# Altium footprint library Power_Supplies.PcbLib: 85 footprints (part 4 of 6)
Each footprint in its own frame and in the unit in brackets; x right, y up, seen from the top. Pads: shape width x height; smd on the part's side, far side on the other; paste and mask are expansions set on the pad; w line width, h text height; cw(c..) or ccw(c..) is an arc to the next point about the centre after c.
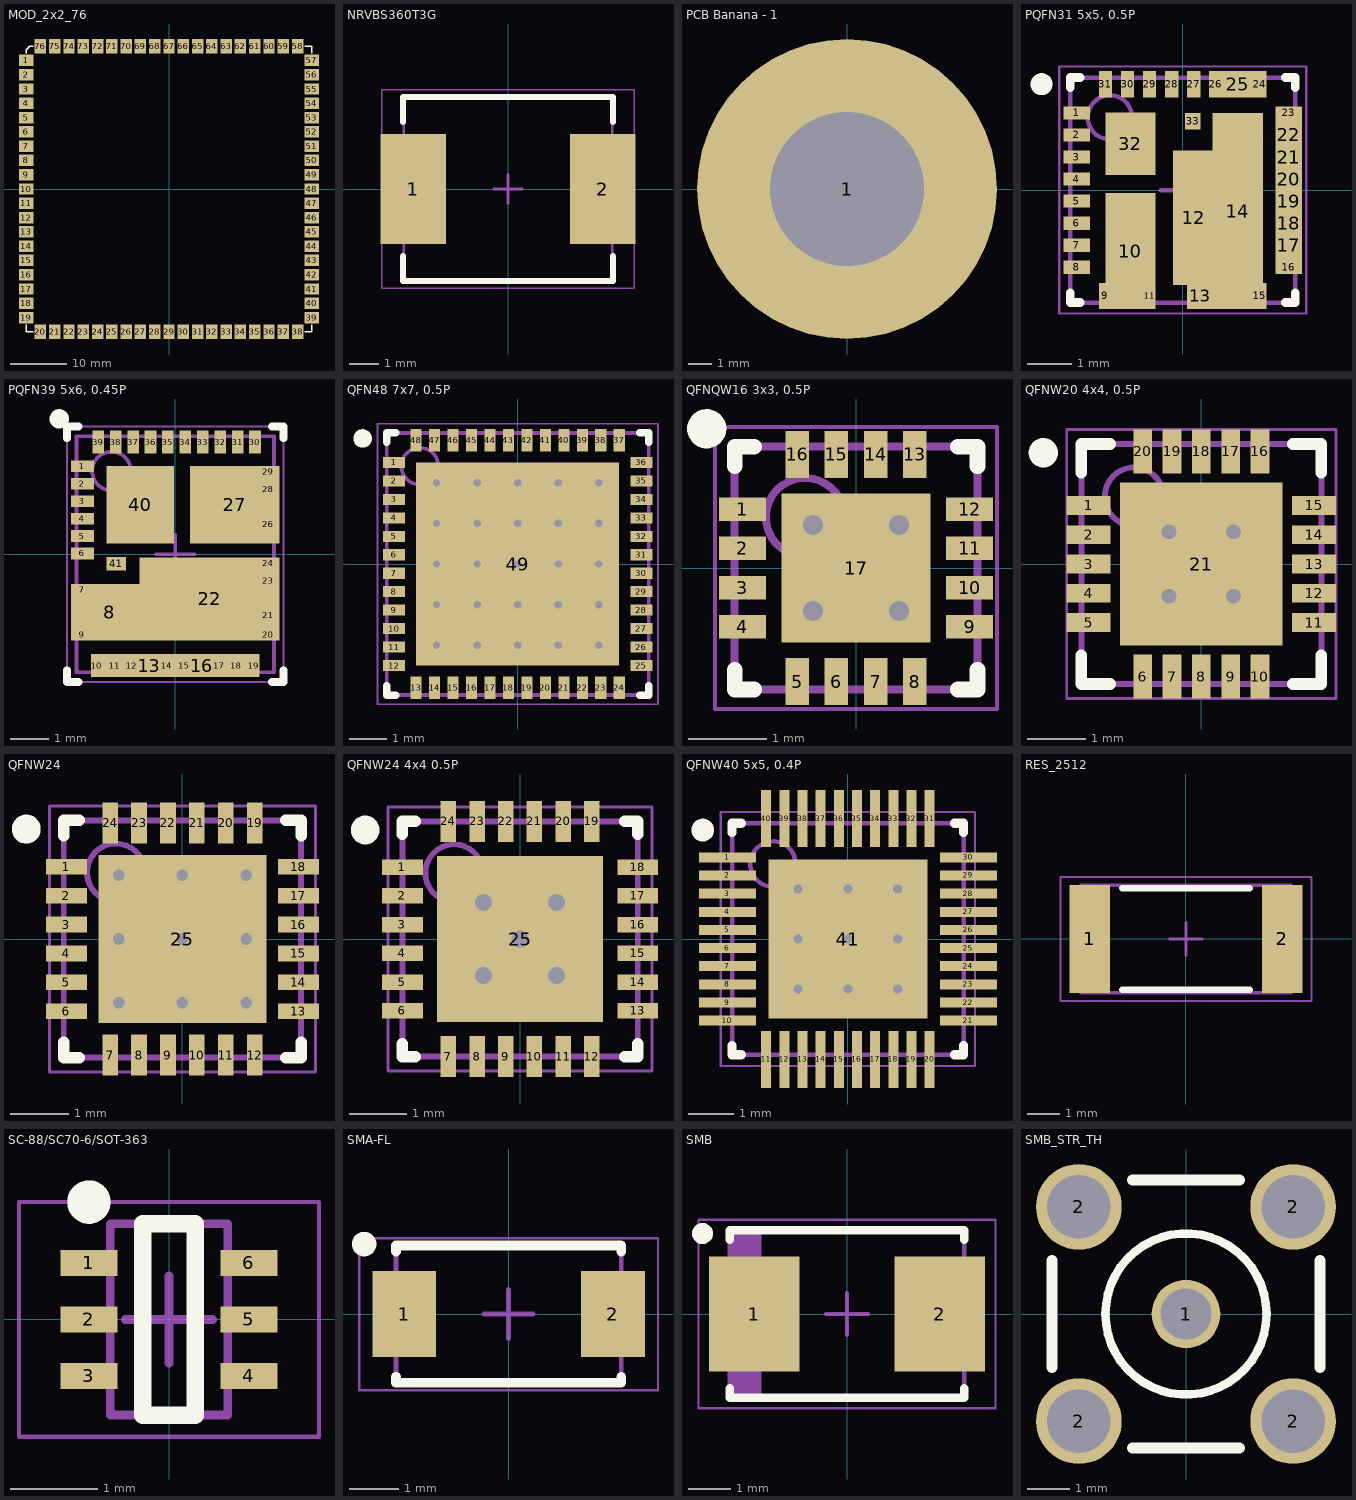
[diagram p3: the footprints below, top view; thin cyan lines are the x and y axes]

## MOD_2x2_76 [mil]
pads (76):
  rect 100x80 smd: 1(-1000,900) 2(-1000,800) 3(-1000,700) 4(-1000,600) 5(-1000,500) 6(-1000,400) 7(-1000,300) 8(-1000,200) 9(-1000,100) 10(-1000,0) 11(-1000,-100) 12(-1000,-200) 13(-1000,-300) 14(-1000,-400) 15(-1000,-500) 16(-1000,-600) 17(-1000,-700) 18(-1000,-800) 19(-1000,-900) 39(1000,-900) 40(1000,-800) 41(1000,-700) 42(1000,-600) 43(1000,-500) 44(1000,-400) 45(1000,-300) 46(1000,-200) 47(1000,-100) 48(1000,0) 49(1000,100) 50(1000,200) 51(1000,300) 52(1000,400) 53(1000,500) 54(1000,600) 55(1000,700) 56(1000,800) 57(1000,900)
  rect 80x100 smd: 20(-900,-1000) 21(-800,-1000) 22(-700,-1000) 23(-600,-1000) 24(-500,-1000) 25(-400,-1000) 26(-300,-1000) 27(-200,-1000) 28(-100,-1000) 29(0,-1000) 30(100,-1000) 31(200,-1000) 32(300,-1000) 33(400,-1000) 34(500,-1000) 35(600,-1000) 36(700,-1000) 37(800,-1000) 38(900,-1000) 58(900,1000) 59(800,1000) 60(700,1000) 61(600,1000) 62(500,1000) 63(400,1000) 64(300,1000) 65(200,1000) 66(100,1000) 67(0,1000) 68(-100,1000) 69(-200,1000) 70(-300,1000) 71(-400,1000) 72(-500,1000) 73(-600,1000) 74(-700,1000) 75(-800,1000) 76(-900,1000)
Top Overlay:
  lines w10: -1000,-950 -1000,-1000 -950,-1000 ; -1000,950 -1000,975 -975,1000 -950,1000 ; 950,-1000 1000,-1000 1000,-950 ; 950,1000 1000,1000 1000,950

## NRVBS360T3G [mm] "NRVBS360T3G"
height 2.61
pads (2):
  rect 2.25x3.79 smd: 1(-3.25,0) 2(3.25,0)
Top Overlay:
  lines w0.2: -3.6,-2.295 -3.6,-3.15 3.6,-3.15 3.6,-2.295 ; -3.6,2.295 -3.6,3.15 3.6,3.15 3.6,2.295
Mechanical 13:
  lines w0.1: -3.575,-3.125 3.575,-3.125 3.575,3.125 -3.575,3.125 -3.575,-3.125
Mechanical 15:
  lines w0.05: -4.325,-3.4 4.325,-3.4 4.325,3.4 -4.325,3.4 -4.325,-3.4
  lines w0.1: -0.5,0 0.5,0 ; 0,-0.5 0,0.5
3D body "NRVBS360T3G.step": height 2.61, standoff 0, extent -3.795,-3.125 3.795,3.125

## PCB Banana - 1 [mil]
pads (1):
  round 500 / inner round 350 / far side round 500 hole 256: 1(0,0)
3D body "SPC15459.step": height 141.73, standoff -488.19, extent -215.51,-187 216.41,187.05

## PQFN31 5x5, 0.5P [mm] "DrMOS"
height 0.8
pads (33):
  rect 0.6x0.3 smd: 1(-2.4,1.75) 2(-2.4,1.25) 3(-2.4,0.75) 4(-2.4,0.25) 5(-2.4,-0.25) 6(-2.4,-0.75) 7(-2.4,-1.25) 8(-2.4,-1.75) 16(2.4,-1.75) 23(2.4,1.75)
  rect 0.3x0.6 smd: 9(-1.75,-2.4) 15(1.75,-2.4) 24(1.75,2.4) 26(0.75,2.4) 27(0.25,2.4) 28(-0.25,2.4) 29(-0.75,2.4) 30(-1.25,2.4) 31(-1.75,2.4)
  rect 1.13x2.63 smd: 10(-1.185,-1.385)
  rect 0.25x0.6 smd: 11(-0.75,-2.4)
  rect 0.94x3.05 smd: 12(0.25,-0.625)
  rect 0.6x0.6 smd: 13(0.4,-2.4)
  rect 1.15x4.45 smd: 14(1.25,-0.475)
  rect 0.6x0.8 smd: 17(2.4,-1.25) 18(2.4,-0.75) 19(2.4,-0.25) 20(2.4,0.25) 21(2.4,0.75) 22(2.4,1.25)
  rect 0.9x0.6 smd: 25(1.25,2.4)
  rect 1.13x1.42 smd: 32(-1.185,1.05)
  rect 0.35x0.38 smd: 33(0.225,1.56)
Top Overlay:
  circle w0.25: c-3.2,2.4 r0.125
  lines w0.2: -2.55,-2.325 -2.55,-2.55 -2.325,-2.55 ; -2.55,2.325 -2.55,2.55 -2.325,2.55 ; 2.325,-2.55 2.55,-2.55 2.55,-2.325 ; 2.325,2.55 2.55,2.55 2.55,2.325
Mechanical 13:
  circle w0.1: c-1.65,1.65 r0.5
  lines w0.1: -2.55,-2.55 2.55,-2.55 2.55,2.55 -2.55,2.55 -2.55,-2.55
Mechanical 15:
  lines w0.05: -2.8,-2.8 2.8,-2.8 2.8,2.8 -2.8,2.8 -2.8,-2.8
  lines w0.1: -0.5,0 0.5,0 ; 0,-0.5 0,0.5
3D body: height 0.8, standoff 0, extent -2.55,-2.55 2.55,2.55

## PQFN39 5x6, 0.45P [mm] "PQFN39 5x6, 0.45P, CASE 483BF, ISSUE O"
height 0.8
pads (41):
  rect 0.6x0.3 smd: 1(-2.4,2.27) 2(-2.4,1.82) 3(-2.4,1.37) 4(-2.4,0.92) 5(-2.4,0.47) 6(-2.4,0.02) 7(-2.4,-0.92) 9(-2.4,-2.08) 20(2.4,-2.08) 21(2.4,-1.58) 23(2.4,-0.68) 24(2.4,-0.23) 26(2.4,0.78) 28(2.4,1.68) 29(2.4,2.13)
  rect 2x1.46 smd: 8(-1.7,-1.5)
  rect 0.3x0.6 smd: 10(-2.03,-2.88) 11(-1.57,-2.88) 12(-1.12,-2.88) 14(-0.22,-2.88) 15(0.23,-2.88) 17(1.13,-2.88) 18(1.58,-2.88) 19(2.03,-2.88) 30(2.06,2.9) 31(1.61,2.9) 32(1.16,2.9) 33(0.71,2.9) 34(0.26,2.9) 35(-0.19,2.9) 36(-0.64,2.9) 37(-1.09,2.9) 38(-1.54,2.9) 39(-1.99,2.9)
  rect 2.5x0.6 smd: 13(-0.67,-2.88) 16(0.68,-2.88)
  rect 3.63x2.15 smd: 22(0.885,-1.155)
  rect 0.6x0.1 smd: 25(2.4,0.33)
  rect 2.32x2 smd: 27(1.54,1.28)
  rect 1.75x2 smd: 40(-0.905,1.28)
  rect 0.5x0.35 smd: 41(-1.53,-0.245)
Top Overlay:
  circle w0.25: c-3,3.5 r0.125
  lines w0.2: -2.8,-3 -2.8,-3.3 -2.5,-3.3 ; -2.8,3 -2.8,3.3 -2.5,3.3 ; 2.5,-3.3 2.8,-3.3 2.8,-3 ; 2.5,3.3 2.8,3.3 2.8,3
Mechanical 13:
  circle w0.1: c-1.65,2.15 r0.5
  lines w0.1: -2.55,-3.05 -2.55,3.05 2.55,3.05 2.55,-3.05 -2.55,-3.05
Mechanical 15:
  lines w0.05: -2.8,-3.3 -2.8,3.3 2.8,3.3 2.8,-3.3 -2.8,-3.3
  lines w0.1: -0.5,0 0.5,0 ; 0,-0.5 0,0.5
3D body "PQFN39 5x6, 0.45P.step": height 0.8, standoff 0, extent -10911.767,-10912.267 -10906.667,-10906.167

## QFN48 7x7, 0.5P [mm] "QFN48 7x7, 0.5P, CASE 485K-02, ISSUE D"
height 1
pads (49):
  rect 0.6x0.3 smd: 1(-3.35,2.75) 2(-3.35,2.25) 3(-3.35,1.75) 4(-3.35,1.25) 5(-3.35,0.75) 6(-3.35,0.25) 7(-3.35,-0.25) 8(-3.35,-0.75) 9(-3.35,-1.25) 10(-3.35,-1.75) 11(-3.35,-2.25) 12(-3.35,-2.75) 25(3.35,-2.75) 26(3.35,-2.25) 27(3.35,-1.75) 28(3.35,-1.25) 29(3.35,-0.75) 30(3.35,-0.25) 31(3.35,0.25) 32(3.35,0.75) 33(3.35,1.25) 34(3.35,1.75) 35(3.35,2.25) 36(3.35,2.75)
  rect 0.3x0.6 smd: 13(-2.75,-3.35) 14(-2.25,-3.35) 15(-1.75,-3.35) 16(-1.25,-3.35) 17(-0.75,-3.35) 18(-0.25,-3.35) 19(0.25,-3.35) 20(0.75,-3.35) 21(1.25,-3.35) 22(1.75,-3.35) 23(2.25,-3.35) 24(2.75,-3.35) 37(2.75,3.35) 38(2.25,3.35) 39(1.75,3.35) 40(1.25,3.35) 41(0.75,3.35) 42(0.25,3.35) 43(-0.25,3.35) 44(-0.75,3.35) 45(-1.25,3.35) 46(-1.75,3.35) 47(-2.25,3.35) 48(-2.75,3.35)
  rect 5.5x5.5 smd: 49(0,0)
via 2.2,-2.2 diameter 0.5 hole 0.2
via 1.1,-2.2 diameter 0.5 hole 0.2
via 0,-2.2 diameter 0.5 hole 0.2
via -1.1,-2.2 diameter 0.5 hole 0.2
via -2.2,-2.2 diameter 0.5 hole 0.2
via 2.2,-1.1 diameter 0.5 hole 0.2
via 1.1,-1.1 diameter 0.5 hole 0.2
via 0,-1.1 diameter 0.5 hole 0.2
via -1.1,-1.1 diameter 0.5 hole 0.2
via -2.2,-1.1 diameter 0.5 hole 0.2
via 2.2,0 diameter 0.5 hole 0.2
via 1.1,0 diameter 0.5 hole 0.2
via 0,0 diameter 0.5 hole 0.2
via -1.1,0 diameter 0.5 hole 0.2
via -2.2,0 diameter 0.5 hole 0.2
via 2.2,1.1 diameter 0.5 hole 0.2
via 1.1,1.1 diameter 0.5 hole 0.2
via 0,1.1 diameter 0.5 hole 0.2
via -1.1,1.1 diameter 0.5 hole 0.2
via -2.2,1.1 diameter 0.5 hole 0.2
via 2.2,2.2 diameter 0.5 hole 0.2
via 1.1,2.2 diameter 0.5 hole 0.2
via 0,2.2 diameter 0.5 hole 0.2
via -1.1,2.2 diameter 0.5 hole 0.2
via -2.2,2.2 diameter 0.5 hole 0.2
Top Overlay:
  circle w0.25: c-4.2,3.4 r0.125
  lines w0.2: -3.55,-3.3 -3.55,-3.55 -3.3,-3.55 ; -3.55,3.3 -3.55,3.55 -3.3,3.55 ; 3.3,-3.55 3.55,-3.55 3.55,-3.3 ; 3.3,3.55 3.55,3.55 3.55,3.3
Mechanical 13:
  circle w0.1: c-2.65,2.65 r0.5
  lines w0.1: -3.55,-3.55 3.55,-3.55 3.55,3.55 -3.55,3.55 -3.55,-3.55
Mechanical 15:
  lines w0.05: -3.8,-3.8 3.8,-3.8 3.8,3.8 -3.8,3.8 -3.8,-3.8
  lines w0.1: -0.5,0 0.5,0 ; 0,-0.5 0,0.5
3D body "QFN48 7x7, 0.5P.step": height 1, standoff 0, extent -3.55,-3.55 3.55,3.55

## QFNQW16 3x3, 0.5P [mm] "QFNQW16 3x3, 0.5P, CASE 484AL, ISSUE A"
height 0.9
pads (17):
  rect 0.6x0.3 smd: 1(-1.45,0.75) 2(-1.45,0.25) 3(-1.45,-0.25) 4(-1.45,-0.75) 9(1.45,-0.75) 10(1.45,-0.25) 11(1.45,0.25) 12(1.45,0.75)
  rect 0.3x0.6 smd: 5(-0.75,-1.45) 6(-0.25,-1.45) 7(0.25,-1.45) 8(0.75,-1.45) 13(0.75,1.45) 14(0.25,1.45) 15(-0.25,1.45) 16(-0.75,1.45)
  rect 1.9x1.9 smd: 17(0,0)
via -0.55,0.55 diameter 0.508 hole 0.254
via 0.55,0.55 diameter 0.508 hole 0.254
via -0.55,-0.55 diameter 0.508 hole 0.254
via 0.55,-0.55 diameter 0.508 hole 0.254
Top Overlay:
  circle w0.25: c-1.905,1.778 r0.125
  lines w0.2: -1.55,-1.3 -1.55,-1.55 -1.3,-1.55 ; -1.55,1.3 -1.55,1.55 -1.3,1.55 ; 1.3,-1.55 1.55,-1.55 1.55,-1.3 ; 1.3,1.55 1.55,1.55 1.55,1.3
Mechanical 13:
  circle w0.1: c-0.65,0.65 r0.5
  lines w0.1: -1.55,-1.55 -1.55,1.55 1.55,1.55 1.55,-1.55 -1.55,-1.55
Mechanical 15:
  lines w0.05: -1.8,-1.8 -1.8,1.8 1.8,1.8 1.8,-1.8 -1.8,-1.8
  lines w0.1: -0.5,0 0.5,0 ; 0,-0.5 0,0.5
3D body "QFNQW16 3x3, 0.5P.step": height 0.9, standoff 0, extent -1.55,-1.55 1.55,1.55

## QFNW20 4x4, 0.5P [mm] "QFNW20 4x4, 0.5P, CASE 484AD, Issue B"
height 0.9
pads (21):
  rect 0.75x0.32 smd: 1(-1.925,1) 2(-1.925,0.5) 3(-1.925,0) 4(-1.925,-0.5) 5(-1.925,-1) 11(1.925,-1) 12(1.925,-0.5) 13(1.925,0) 14(1.925,0.5) 15(1.925,1)
  rect 0.32x0.75 smd: 6(-1,-1.925) 7(-0.5,-1.925) 8(0,-1.925) 9(0.5,-1.925) 10(1,-1.925) 16(1,1.925) 17(0.5,1.925) 18(0,1.925) 19(-0.5,1.925) 20(-1,1.925)
  rect 2.78x2.78 smd: 21(0,0)
via 0.55,-0.55 diameter 0.508 hole 0.254
via -0.55,-0.55 diameter 0.508 hole 0.254
via 0.55,0.55 diameter 0.508 hole 0.254
via -0.55,0.55 diameter 0.508 hole 0.254
Top Overlay:
  circle w0.25: c-2.7,1.9 r0.125
  lines w0.2: -2.05,-1.56 -2.05,-2.05 -1.56,-2.05 ; -2.05,1.56 -2.05,2.05 -1.56,2.05 ; 1.56,-2.05 2.05,-2.05 2.05,-1.56 ; 1.56,2.05 2.05,2.05 2.05,1.56
Mechanical 13:
  circle w0.1: c-1.15,1.15 r0.5
  lines w0.1: -2.05,-2.05 2.05,-2.05 2.05,2.05 -2.05,2.05 -2.05,-2.05
Mechanical 15:
  lines w0.05: -2.3,-2.3 2.3,-2.3 2.3,2.3 -2.3,2.3 -2.3,-2.3
  lines w0.1: -0.5,0 0.5,0 ; 0,-0.5 0,0.5
3D body "QFNW20 4x4, 0.5P.step": height 0.9, standoff 0, extent -2.05,-2.05 2.05,2.05

## QFNW24 [mm] "QFNW24 4x4, 0.5P, CASE 484AE, Issue A"
height 0.9
pads (25):
  rect 0.71x0.27 smd: 1(-2.005,1.25) 2(-2.005,0.75) 3(-2.005,0.25) 4(-2.005,-0.25) 5(-2.005,-0.75) 6(-2.005,-1.25) 13(2.005,-1.25) 14(2.005,-0.75) 15(2.005,-0.25) 16(2.005,0.25) 17(2.005,0.75) 18(2.005,1.25)
  rect 0.27x0.71 smd: 7(-1.25,-2.005) 8(-0.75,-2.005) 9(-0.25,-2.005) 10(0.25,-2.005) 11(0.75,-2.005) 12(1.25,-2.005) 19(1.25,2.005) 20(0.75,2.005) 21(0.25,2.005) 22(-0.25,2.005) 23(-0.75,2.005) 24(-1.25,2.005)
  rect 2.9x2.9 smd: 25(0,0)
via 1.1,-1.1 diameter 0.5 hole 0.2
via 0,-1.1 diameter 0.5 hole 0.2
via -1.1,-1.1 diameter 0.5 hole 0.2
via 1.1,0 diameter 0.5 hole 0.2
via 0,0 diameter 0.5 hole 0.2
via -1.1,0 diameter 0.5 hole 0.2
via 1.1,1.1 diameter 0.5 hole 0.2
via 0,1.1 diameter 0.5 hole 0.2
via -1.1,1.1 diameter 0.5 hole 0.2
Top Overlay:
  circle w0.25: c-2.7,1.9 r0.125
  lines w0.2: -2.05,-1.785 -2.05,-2.05 -1.785,-2.05 ; -2.05,1.785 -2.05,2.05 -1.785,2.05 ; 1.785,-2.05 2.05,-2.05 2.05,-1.785 ; 1.785,2.05 2.05,2.05 2.05,1.785
Mechanical 13:
  circle w0.1: c-1.15,1.15 r0.5
  lines w0.1: -2.05,-2.05 2.05,-2.05 2.05,2.05 -2.05,2.05 -2.05,-2.05
Mechanical 15:
  lines w0.05: -2.3,-2.3 2.3,-2.3 2.3,2.3 -2.3,2.3 -2.3,-2.3
  lines w0.1: -0.5,0 0.5,0 ; 0,-0.5 0,0.5
3D body "QFNW24.step": height 0.9, standoff 0, extent -2.05,-2.05 2.05,2.05

## QFNW24 4x4 0.5P [mm] "QFNW, 24-Leads, Body 4.00x4.00mm, Pitch 0.50mm, Thermal Pad 2.80x2.80mm, IPC Medium Density"
height 0.9
pads (25):
  rect 0.71x0.27 smd: 1(-2.05,1.25) 2(-2.05,0.75) 3(-2.05,0.25) 4(-2.05,-0.25) 5(-2.05,-0.75) 6(-2.05,-1.25) 13(2.05,-1.25) 14(2.05,-0.75) 15(2.05,-0.25) 16(2.05,0.25) 17(2.05,0.75) 18(2.05,1.25)
  rect 0.27x0.71 smd: 7(-1.25,-2.05) 8(-0.75,-2.05) 9(-0.25,-2.05) 10(0.25,-2.05) 11(0.75,-2.05) 12(1.25,-2.05) 19(1.25,2.05) 20(0.75,2.05) 21(0.25,2.05) 22(-0.25,2.05) 23(-0.75,2.05) 24(-1.25,2.05)
  rect 2.9x2.9 smd: 25(0,0)
via 0.635,0.635 diameter 0.6 hole 0.3
via -0.635,0.635 diameter 0.6 hole 0.3
via -0.635,-0.635 diameter 0.6 hole 0.3
via 0.635,-0.635 diameter 0.6 hole 0.3
via 0,0 diameter 0.6 hole 0.3
Top Overlay:
  circle w0.25: c-2.7,1.9 r0.125
  lines w0.2: -2.05,-1.825 -2.05,-2.05 -1.825,-2.05 ; -2.05,1.825 -2.05,2.05 -1.825,2.05 ; 1.825,-2.05 2.05,-2.05 2.05,-1.825 ; 1.825,2.05 2.05,2.05 2.05,1.825
Mechanical 13:
  circle w0.1: c-1.15,1.15 r0.5
  lines w0.1: -2.05,-2.05 -2.05,2.05 2.05,2.05 2.05,-2.05 -2.05,-2.05
Mechanical 15:
  lines w0.05: -2.3,-2.3 -2.3,2.3 2.3,2.3 2.3,-2.3 -2.3,-2.3
  lines w0.1: -0.5,0 0.5,0 ; 0,-0.5 0,0.5
3D body "PQFN50P400X400X90_HS-25N.step": height 0.9, standoff 0, extent -2.05,-2.05 2.05,2.05

## QFNW40 5x5, 0.4P [mm]
height 0.9
pads (41):
  rect 1.26x0.22 smd: 1(-2.655,1.8) 2(-2.655,1.4) 3(-2.655,1) 4(-2.655,0.6) 5(-2.655,0.2) 6(-2.655,-0.2) 7(-2.655,-0.6) 8(-2.655,-1) 9(-2.655,-1.4) 10(-2.655,-1.8) 21(2.655,-1.8) 22(2.655,-1.4) 23(2.655,-1) 24(2.655,-0.6) 25(2.655,-0.2) 26(2.655,0.2) 27(2.655,0.6) 28(2.655,1) 29(2.655,1.4) 30(2.655,1.8)
  rect 0.22x1.26 smd: 11(-1.8,-2.655) 12(-1.4,-2.655) 13(-1,-2.655) 14(-0.6,-2.655) 15(-0.2,-2.655) 16(0.2,-2.655) 17(0.6,-2.655) 18(1,-2.655) 19(1.4,-2.655) 20(1.8,-2.655) 31(1.8,2.655) 32(1.4,2.655) 33(1,2.655) 34(0.6,2.655) 35(0.2,2.655) 36(-0.2,2.655) 37(-0.6,2.655) 38(-1,2.655) 39(-1.4,2.655) 40(-1.8,2.655)
  rect 3.5x3.5 smd: 41(0,0)
via 1.1,-1.1 diameter 0.406 hole 0.203
via 0,-1.1 diameter 0.406 hole 0.203
via -1.1,-1.1 diameter 0.406 hole 0.203
via 1.1,0 diameter 0.406 hole 0.203
via 0,0 diameter 0.406 hole 0.203
via -1.1,0 diameter 0.406 hole 0.203
via 1.1,1.1 diameter 0.406 hole 0.203
via 0,1.1 diameter 0.406 hole 0.203
via -1.1,1.1 diameter 0.406 hole 0.203
Top Overlay:
  circle w0.25: c-3.2,2.4 r0.125
  lines w0.2: -2.55,-2.35 -2.55,-2.55 -2.35,-2.55 ; -2.55,2.35 -2.55,2.55 -2.35,2.55 ; 2.35,-2.55 2.55,-2.55 2.55,-2.35 ; 2.35,2.55 2.55,2.55 2.55,2.35
Mechanical 13:
  circle w0.1: c-1.65,1.65 r0.5
  lines w0.1: -2.55,-2.55 2.55,-2.55 2.55,2.55 -2.55,2.55 -2.55,-2.55
Mechanical 15:
  lines w0.05: -2.8,-2.8 2.8,-2.8 2.8,2.8 -2.8,2.8 -2.8,-2.8
  lines w0.1: -0.5,0 0.5,0 ; 0,-0.5 0,0.5
3D body: height 0.9, standoff 0, extent -2.55,-2.55 2.55,2.55

## RES_2512 [mm] "Chip Resistor, 2-Leads, Body 6.30x3.15mm, IPC Medium Density"
height 0.65
pads (2):
  rect 1.25x3.3 smd: 1(-2.95,0) 2(2.95,0)
Top Overlay:
  lines w0.2: -1.95,-1.55 1.95,-1.55 ; -1.95,1.55 1.95,1.55
Mechanical 13:
  lines w0.1: -3.225,-1.65 -3.225,1.65 3.225,1.65 3.225,-1.65 -3.225,-1.65
Mechanical 15:
  lines w0.05: -3.85,-1.9 -3.85,1.9 3.85,1.9 3.85,-1.9 -3.85,-1.9
  lines w0.1: -0.5,0 0.5,0 ; 0,-0.5 0,0.5
3D body "RES_2512.step": height 0.65, standoff 0, extent -3.225,-1.65 3.225,1.65

## SC-88/SC70-6/SOT-363 [mm] "SC-88/SC70-6/SOT-363, CASE 419B-02, Issue Y"
height 1.1
pads (6):
  rect 0.66x0.3 smd: 1(-0.92,0.65) 2(-0.92,0) 3(-0.92,-0.65) 4(0.92,-0.65) 5(0.92,0) 6(0.92,0.65)
Top Overlay:
  circle w0.25: c-0.92,1.35 r0.125
  lines w0.2: -0.3,-1.1 0.3,-1.1 0.3,1.1 -0.3,1.1 -0.3,-1.1
Mechanical 13:
  lines w0.1: -0.675,-1.1 -0.675,1.1 0.675,1.1 0.675,-1.1 -0.675,-1.1
Mechanical 15:
  lines w0.05: -1.725,-1.35 -1.725,1.35 1.725,1.35 1.725,-1.35 -1.725,-1.35
  lines w0.1: -0.5,0 0.5,0 ; 0,-0.5 0,0.5
3D body "SOT23127P600-8N.step": height 1.1, standoff 0, extent -1.1,-1.1 1.1,1.1

## SMA-FL [mm] "SMA-FL, CASE 403AA-01, ISSUE O"
height 1.1
pads (2):
  rect 1.3x1.76 smd: 1(-2.13,0) 2(2.13,0)
Top Overlay:
  circle w0.25: c-2.95,1.43 r0.125
  lines w0.2: -2.3,-1.28 -2.3,-1.4 2.3,-1.4 2.3,-1.28 ; -2.3,1.28 -2.3,1.4 2.3,1.4 2.3,1.28
Mechanical 13:
  lines w0.1: -2.3,-1.4 -2.3,1.4 2.3,1.4 2.3,-1.4 -2.3,-1.4
Mechanical 15:
  lines w0.05: -3.05,-1.55 -3.05,1.55 3.05,1.55 3.05,-1.55 -3.05,-1.55
  lines w0.1: -0.5,0 0.5,0 ; 0,-0.5 0,0.5
3D body "SMA-FL.step": height 1.1, standoff 0, extent -2.55,-1.4 2.55,1.4

## SMB [mil] "SMB, CASE403A-03, ISSUE J"
height 97.24
pads (2):
  rect 85x107.99 smd: 1(-87.01,0) 2(87.01,0)
Top Overlay:
  circle w9.84: c-135.83,75.65 r4.92
  lines w7.87: -110.24,-69.74 -110.24,-78.74 110.24,-78.74 110.24,-69.74 ; -110.24,69.74 -110.24,78.74 110.24,78.74 110.24,69.74
Mechanical 13:
  rectangle: -110.24,-77.76 -80.58,77.76
  lines w3.94: -110.24,-77.76 -110.24,77.76 110.24,77.76 110.24,-77.76 -110.24,-77.76
Mechanical 15:
  lines w1.97: -139.76,-88.58 -139.76,88.58 139.76,88.58 139.76,-88.58 -139.76,-88.58
  lines w3.94: -19.69,0 19.68,0 ; 0,-19.68 0,19.69
3D body "SMB-2.step": height 97.24, standoff 0, extent -118.9,-77.76 118.9,77.76

## SMB_STR_TH [mil]
pads (5):
  round 64 hole 48: 1(0,0)
  round 80 hole 59.5: 2(-100,-100) 2(-100,100) 2(100,-100) 2(100,100)
Top Overlay:
  circle w8: c0,0 r75.17
  lines w10: -125,-50 -125,50 ; -50,-125 50,-125 ; -50,125 50,125 ; 125,-50 125,50
3D body "SMB_jack_50_Ohm.step": height 299.76, standoff -153, extent -137.79,-137.79 137.8,137.8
